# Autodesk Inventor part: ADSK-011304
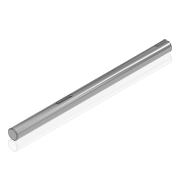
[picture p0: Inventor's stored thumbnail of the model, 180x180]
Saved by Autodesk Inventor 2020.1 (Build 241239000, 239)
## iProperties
Created: 1999-11
Part Number: ADSK-011304
Material: Acier doux
Description: SHFT2K,RG,CX,10,160,SHAFT,DRIVE
Document SubType Name: Modeling
Designer: sspink
Density: 7.86 g/cm^3
Appearance: Chrom - poliert
Mass: 1606.43 g
Surface Area: 336.475 cm^2
Volume: 204.38 cm^3
Control State: 0
Checked Out: False
Last Check In By: sspink
Last Check In Date: 1999-12-22
Master: False
Shininess: 0.0
Length Units: 11269
Angle Units: 11279
Time Units: 11290
Mass Units: 11283
Length Display Precision: 3
Angle Display Precision: 2
Compacted: True
Dimensions: 25,4x25,4x406 mm
Mass: 1,606 kg
DocNumber: ADSK-011304.ipt
Folder: 01 - Themengebiete\Simplification\01 - Packaging machine\
VDS_Category: 3D Komponenten
Density: 0.0
Volumn: 0.0
Area: 0.0
PropertySet Name: Model Information
Author: sspink
Revision Number: -
Title: SHFT2K,RG,CX,10,160,SHAFT,DRIVE
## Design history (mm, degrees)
node "Solide1"
  node "Extrusion1" dims "d0" = 406, "d1" = 0
  node "Extrusion3" dims "d8" = 40, "d9" = 0
  node "Chamfer1" dims "d10" = 1.5, "d11" = 1.5, "d16" = 45 deg
  node "Extrusion4" dims "d14" = 30, "d15" = 0
workplane "Work Plane1"
sketch "Sketch3"
  geometry: L1 (-3, 12.341)-(-3, 9.7); L2 (-3, 9.7)-(3, 9.7); L3 (3, 9.7)-(3, 12.341); A1 r 12.7 centre (0, 0) between (-3, 12.341) and (3, 12.341) reference; 1 further point
  constraints: 6 end point, 2 perpendicular, 2 point on circle, 1 midpoint, 1 vertical, 1 vertical alignment
  dimensions: "d17" = 6 distance of L1.end L2.end; "d18" = 3 distance edge to line of A1 L2
  node "Projizierte Kontur1"
workplane "Arbeitsebene3"
workaxis "Work Axis1"
sketch "Sketch4"
  geometry: L1 (3, 12.341)-(3, 9.7) reference; L2 (3, 9.7)-(-3, 9.7) reference; L3 (-3, 9.7)-(-3, 12.341) reference; A1 r 12.7 centre (0, 0) between (3, 12.341) and (-3, 12.341) reference
fillet "Rundung1"
fillet "Rundung2"
fillet "Rundung3"
node "Corps solides"
node "Corps surfaciques"
sketch "Sketch1"
  geometry: C1 r 12.7 at (0, 0)
  constraints: 1 centre point
  dimensions: "d12" = 25.4 diameter of C1
other parameters: "d7" = -135
